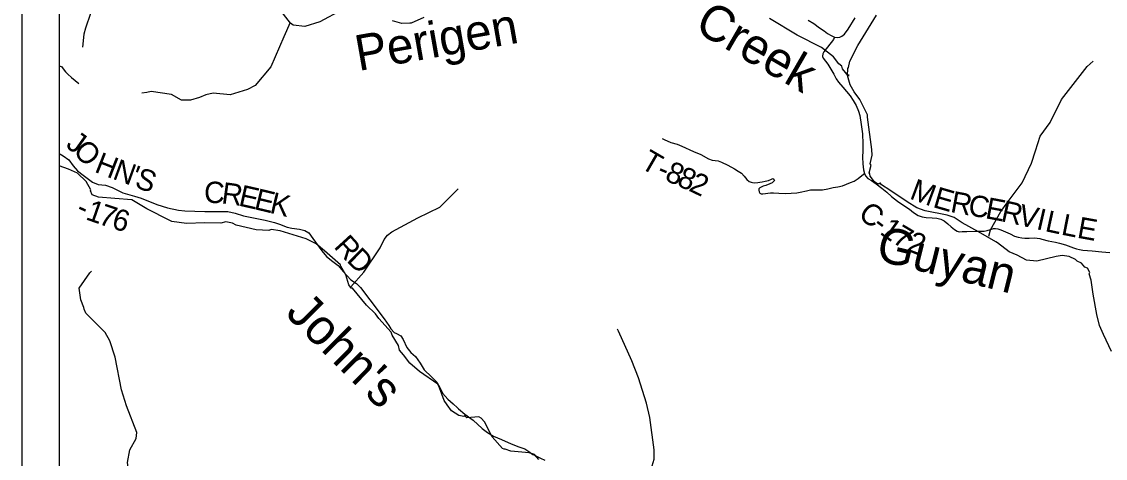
# Model space of a CAD drawing. Extents: x -1.8 to 75.7, y -2 to 25.
# Drawn here: x 43.7 to 46.582, y 17.434 to 18.595 of the extents above; entities that cross this region are included whole.
import ezdxf

# ---------------------------------------------------------------- set-up
doc = ezdxf.new("R2010")
doc.units = 0
for name, color, linetype in [('GM_X_County_Road', 7, 'Continuous'), ('GM_X_County_Road_Text', 7, 'Continuous'), ('GM_X_Minor_River', 7, 'Continuous'), ('GM_X_Minor_River_Text', 7, 'Continuous'), ('GM_X_State_Route', 7, 'Continuous'), ('GM_X_Township', 7, 'Continuous'), ('GM_X_Township_Road', 7, 'Continuous'), ('GM_X_Township_Road_Text', 7, 'Continuous'), ('SH_Data', 7, 'Continuous')]:
    doc.layers.add(name, color=color, linetype=linetype)

msp = doc.modelspace()

# ---------------------------------------------------------------- linework, layer by layer
at = {"layer": 'GM_X_County_Road'}
for points in [[(45.8619, 18.5535), (45.8589, 18.5478), (45.8339, 18.515), (45.8307, 18.5096), (45.8298, 18.5031)], [(45.8298, 18.5031), (45.8298, 18.5028), (45.8313, 18.498), (45.8376, 18.4898), (45.844, 18.4824), (45.8493, 18.4735), (45.8552, 18.4645), (45.8601, 18.455), (45.8664, 18.443), (45.8723, 18.434), (45.8843, 18.4208), (45.894, 18.4096), (45.9032, 18.3978), (45.9113, 18.3858), (45.9191, 18.3718), (45.9254, 18.3574), (45.9288, 18.3456), (45.9331, 18.3214), (45.9359, 18.2972), (45.9369, 18.2704), (45.9371, 18.2515), (45.9365, 18.235), (45.9369, 18.2175), (45.9386, 18.2013), (45.9416, 18.1915), (45.9443, 18.1848), (45.9506, 18.1785), (45.9603, 18.1728), (45.9727, 18.164), (45.9874, 18.1527), (46.0012, 18.1415), (46.0134, 18.1305), (46.0295, 18.1181), (46.0487, 18.1048), (46.061, 18.0963), (46.0719, 18.0877), (46.0845, 18.0802), (46.0952, 18.0761), (46.1059, 18.0746), (46.1216, 18.074), (46.1338, 18.0727), (46.1447, 18.0697), (46.1533, 18.0652), (46.1637, 18.0573), (46.1721, 18.05), (46.1809, 18.0427), (46.1882, 18.0382), (46.1933, 18.0365), (46.2012, 18.037), (46.2141, 18.0376), (46.2368, 18.038), (46.2601, 18.0382), (46.2676, 18.0395), (46.279, 18.0432), (46.285, 18.0449), (46.2901, 18.0453), (46.2965, 18.0445), (46.3042, 18.0421), (46.3289, 18.0307), (46.3406, 18.0252), (46.3505, 18.022), (46.3597, 18.02), (46.3683, 18.0192), (46.3798, 18.0192), (46.3931, 18.02), (46.401, 18.0196), (46.4077, 18.019), (46.4135, 18.0168), (46.4302, 18.0121), (46.4492, 18.0085), (46.4606, 18.0065), (46.4764, 18.0014), (46.4978, 17.9939), (46.5055, 17.9916), (46.5135, 17.9898), (46.5227, 17.9879), (46.5475, 17.9856), (46.5726, 17.9832), (46.5938, 17.9811)], [(43.8002, 18.2448), (43.8107, 18.2383), (43.8257, 18.2278), (43.8369, 18.2121), (43.849, 18.1989), (43.8637, 18.1873), (43.8745, 18.1788), (43.8884, 18.168), (43.9036, 18.1624), (43.9233, 18.1606), (43.9412, 18.1539), (43.9688, 18.1398), (44.0001, 18.1308), (44.0178, 18.1255), (44.0597, 18.1093), (44.0884, 18.0999), (44.1168, 18.0939), (44.1341, 18.0919), (44.1872, 18.0905), (44.2481, 18.0901), (44.2676, 18.086), (44.2902, 18.0786), (44.3475, 18.067), (44.3729, 18.0616), (44.3861, 18.0571), (44.4058, 18.0491), (44.4188, 18.0459), (44.4387, 18.0436), (44.4528, 18.0397), (44.4636, 18.0334), (44.4748, 18.0186), (44.4983, 17.9859), (44.5106, 17.9711), (44.5276, 17.9575), (44.5422, 17.9465), (44.5561, 17.9301), (44.5758, 17.9091), (44.5906, 17.8992), (44.6011, 17.8883), (44.6262, 17.8558), (44.6643, 17.8047), (44.6763, 17.7877), (44.6819, 17.7785), (44.6912, 17.7689), (44.6966, 17.7662)], [(44.6966, 17.7662), (44.7088, 17.7599), (44.7144, 17.7501), (44.7245, 17.7288), (44.7353, 17.7153), (44.7474, 17.7046), (44.7597, 17.6873), (44.7706, 17.6699), (44.7904, 17.6506), (44.804, 17.6365), (44.8123, 17.6226), (44.8197, 17.6072), (44.8334, 17.5919), (44.8477, 17.5796), (44.8588, 17.5685)], [(44.8588, 17.5685), (44.8616, 17.5657), (44.8788, 17.5521), (44.9008, 17.5357), (44.9252, 17.5138), (44.9393, 17.5026), (44.9552, 17.4934), (44.976, 17.4842), (45.0016, 17.4732), (45.022, 17.4652), (45.0379, 17.4593), (45.0493, 17.4526), (45.0596, 17.4448), (45.0608, 17.4442)], [(45.0608, 17.4442), (45.08, 17.4349), (45.0918, 17.4291)]]:
    msp.add_lwpolyline(points, dxfattribs=at)
at = {"layer": 'GM_X_Minor_River'}
for points in [[(44.5528, 18.6262), (44.4927, 18.5942), (44.4534, 18.5823), (44.4224, 18.586), (44.4148, 18.5913), (44.3845, 18.6312)], [(43.8833, 18.617), (43.8701, 18.5778), (43.8652, 18.5615), (43.8615, 18.5269)], [(44.414, 18.5924), (44.3974, 18.555), (44.3632, 18.4748), (44.3212, 18.4256), (44.3009, 18.4149), (44.2547, 18.4008), (44.2091, 18.4045), (44.1901, 18.4009), (44.1732, 18.3935), (44.1488, 18.3859), (44.125, 18.3867), (44.0983, 18.4016), (44.0444, 18.409), (44.0327, 18.4071), (44.0194, 18.4049)], [(44.7694, 18.6059), (44.7358, 18.5906), (44.7324, 18.5906), (44.7112, 18.5905), (44.6862, 18.5969)], [(45.8973, 18.45), (45.8994, 18.4544), (45.8991, 18.4502), (45.8828, 18.4695), (45.8813, 18.4764), (45.8737, 18.4828), (45.8589, 18.5014), (45.8275, 18.5264), (45.7629, 18.5593), (45.6891, 18.6032)], [(46.5987, 17.718), (46.5775, 17.7635), (46.5665, 17.7878), (46.5597, 17.8167), (46.5498, 17.8703), (46.5445, 17.9075), (46.5388, 17.925), (46.5407, 17.928), (46.535, 17.9394), (46.5278, 17.9428), (46.5184, 17.9534), (46.507, 17.9583), (46.5032, 17.9629), (46.4858, 17.9708), (46.4677, 17.9738), (46.4514, 17.9711), (46.4004, 17.9588), (46.3728, 17.9614), (46.3475, 17.9747), (46.3263, 17.9834), (46.2953, 18.0069), (46.2911, 18.0095), (46.245, 18.0364), (46.2011, 18.0602), (46.1803, 18.0742), (46.1618, 18.0807), (46.1028, 18.0923), (46.0805, 18.1002), (46.0555, 18.1157), (46.0093, 18.1472), (45.987, 18.1616), (45.9836, 18.1669), (45.9814, 18.1646), (45.984, 18.1635), (45.9817, 18.1638), (45.9832, 18.1657), (45.9772, 18.1634), (45.9685, 18.1691), (45.9564, 18.1839), (45.956, 18.1904), (45.9541, 18.193), (45.9594, 18.2132), (45.9571, 18.217), (45.9616, 18.2398), (45.9609, 18.2554), (45.9494, 18.3412), (45.9494, 18.3469), (45.9294, 18.3883), (45.9138, 18.4088), (45.9032, 18.427), (45.8968, 18.4521), (45.8971, 18.4703), (45.899, 18.4734), (45.9024, 18.4897), (45.9236, 18.5316), (45.9737, 18.6119)], [(46.2721, 18.0246), (46.2766, 18.0415), (46.3042, 18.09), (46.3212, 18.1134), (46.3609, 18.1664), (46.386, 18.2188), (46.3968, 18.2518), (46.4085, 18.2902), (46.4354, 18.3269), (46.4655, 18.3878), (46.5336, 18.4757), (46.5499, 18.49)], [(44.617, 17.8411), (44.5799, 17.887), (44.5762, 17.887), (44.5701, 17.8957), (44.5621, 17.9223), (44.5493, 17.9451), (44.5477, 17.9485), (44.5054, 17.986), (44.4834, 18.0046), (44.4566, 18.0179), (44.3878, 18.0393), (44.3636, 18.0427), (44.3571, 18.04), (44.3242, 18.0419), (44.2706, 18.0543), (44.2607, 18.0592), (44.2433, 18.0626), (44.2297, 18.0591), (44.1874, 18.0605), (44.1383, 18.0589), (44.0993, 18.0641), (44.0944, 18.0664), (44.0331, 18.0978), (43.9934, 18.1216), (43.9477, 18.1246), (43.9046, 18.1283), (43.8876, 18.1347), (43.883, 18.1449), (43.8845, 18.1476), (43.8716, 18.17), (43.8489, 18.1927), (43.8244, 18.2033), (43.8002, 18.2118)], [(44.5757, 17.8903), (44.6099, 17.9295), (44.6539, 17.9935), (44.6644, 18.0159), (44.673, 18.0278), (44.6843, 18.0366), (44.7539, 18.0734), (44.8126, 18.1022), (44.8612, 18.1503)], [(43.9314, 17.2896), (43.9461, 17.3223), (43.968, 17.3463), (43.9837, 17.3659), (43.9864, 17.392), (43.9817, 17.423), (43.9876, 17.4566), (44.0044, 17.4875), (44.0064, 17.5034), (43.9791, 17.5738), (43.9656, 17.6167), (43.949, 17.7031), (43.9344, 17.7465), (43.9226, 17.7685), (43.8712, 17.8202), (43.8666, 17.8306), (43.8653, 17.8356), (43.8576, 17.856), (43.8528, 17.8865), (43.8817, 17.9274), (43.8863, 17.9318)], [(45.0756, 17.4315), (45.0638, 17.4443), (45.0498, 17.4493), (45.0014, 17.4537), (44.9863, 17.459), (44.9833, 17.459), (44.9791, 17.4601), (44.9511, 17.4919), (44.9307, 17.531), (44.9224, 17.5413), (44.9159, 17.5443), (44.8838, 17.5419), (44.8789, 17.5469), (44.8759, 17.5457), (44.8626, 17.5483), (44.843, 17.5608), (44.8316, 17.5768), (44.824, 17.5878), (44.8089, 17.6284), (44.807, 17.6318), (44.7586, 17.6651), (44.7325, 17.6871), (44.7154, 17.7091), (44.7052, 17.7216), (44.7026, 17.7342), (44.6851, 17.7619), (44.6825, 17.7695), (44.6499, 17.8059), (44.6409, 17.8184), (44.617, 17.8411)], [(45.3634, 17.3541), (45.3715, 17.3971), (45.382, 17.4317), (45.382, 17.4571), (45.371, 17.5429), (45.3616, 17.5812), (45.3409, 17.6483), (45.323, 17.6933), (45.2876, 17.7726), (45.2847, 17.7773)]]:
    msp.add_lwpolyline(points, dxfattribs=at)
at = {"layer": 'GM_X_State_Route'}
msp.add_lwpolyline([(45.7914, 18.5993), (45.8068, 18.5898), (45.822, 18.5789), (45.834, 18.5706), (45.8433, 18.5639), (45.8526, 18.558), (45.8619, 18.5535), (45.8687, 18.5527), (45.876, 18.5537), (45.8813, 18.5562), (45.8883, 18.5615), (45.8978, 18.575), (45.9172, 18.6054)], dxfattribs=at)
at = {"layer": 'GM_X_Township'}
msp.add_lwpolyline([(43.8002, 18.978), (43.8002, 15.7121), (47.7632, 15.7121)], dxfattribs=at)
at = {"layer": 'GM_X_Township_Road'}
for points in [[(43.8002, 18.4774), (43.8011, 18.4775), (43.8071, 18.475), (43.8109, 18.4694), (43.8169, 18.4619), (43.8226, 18.4555), (43.8327, 18.4466), (43.8525, 18.4306)], [(45.4033, 18.2842), (45.4086, 18.2816), (45.4263, 18.274), (45.4433, 18.2692), (45.4557, 18.2641), (45.4871, 18.2496), (45.5066, 18.2415), (45.5267, 18.2301), (45.5362, 18.2269), (45.5525, 18.2254), (45.5615, 18.2214), (45.5785, 18.2137), (45.5958, 18.2035), (45.606, 18.1972), (45.6149, 18.1923), (45.6212, 18.184), (45.6289, 18.1756), (45.6352, 18.1703), (45.6401, 18.1683), (45.644, 18.1671), (45.6499, 18.1669), (45.6584, 18.1673), (45.6629, 18.1681), (45.6698, 18.1693), (45.6779, 18.1706), (45.6863, 18.1732), (45.6942, 18.1767), (45.6975, 18.1779), (45.7009, 18.1764), (45.7019, 18.1728), (45.6999, 18.1702), (45.6958, 18.1669), (45.6895, 18.1643), (45.679, 18.1596), (45.6722, 18.1574), (45.6631, 18.1535), (45.6609, 18.1506), (45.6605, 18.147), (45.6615, 18.1425), (45.6631, 18.1388), (45.6668, 18.1378), (45.6716, 18.1378), (45.6781, 18.1384), (45.6842, 18.139), (45.6916, 18.1401), (45.6993, 18.1401), (45.7141, 18.1392), (45.7328, 18.1386), (45.7465, 18.139), (45.7615, 18.1399), (45.7708, 18.1421), (45.7871, 18.1455), (45.7979, 18.1476), (45.8064, 18.1482), (45.82, 18.1478), (45.83, 18.1482), (45.8442, 18.1506), (45.8579, 18.1543), (45.8707, 18.1557), (45.8835, 18.1586), (45.8936, 18.1628), (45.9044, 18.1673), (45.9142, 18.171), (45.9195, 18.1744), (45.9251, 18.1781), (45.9347, 18.186), (45.9416, 18.1915)]]:
    msp.add_lwpolyline(points, dxfattribs=at)
at = {"layer": 'SH_Data'}
for p, q in [((43.7002, 22.6121), (43.7002, 15.6121)), ((43.8002, 22.5121), (43.8002, 15.7121)), ((43.8002, 22.5121), (43.8002, 15.7121))]:
    msp.add_line(p, q, dxfattribs=at)

# ---------------------------------------------------------------- texts
at = {"layer": 'GM_X_County_Road_Text'}
for s, rotation, p in [('J', 324.8161, (43.815, 18.2626)), ('O', 312.4504, (43.8344, 18.2493)), ('H', 338.6262, (43.8913, 18.1965)), ('N', 340.0241, (43.9393, 18.1778)), ('S', 339.5641, (43.9978, 18.1564)), ("'", 339.6384, (43.9861, 18.1607)), ('C', 358.3976, (44.1846, 18.1136)), ('R', 352.3609, (44.2297, 18.1124)), ('E', 347.2922, (44.2747, 18.1065)), ('M', 339.67, (46.0591, 18.1255)), ('E', 346.5843, (44.3159, 18.0972)), ('K', 346.5848, (44.3573, 18.0873)), ('E', 343.7296, (46.1211, 18.1027)), ('R', 349.4099, (46.1679, 18.0894)), ('C', 350.5171, (46.215, 18.0806)), ('E', 349.3137, (46.2607, 18.0729)), ('-', 335.3927, (43.8412, 18.082)), ('1', 340.8123, (43.8679, 18.0701)), ('7', 341.1906, (43.9013, 18.0585)), ('C', 321.9763, (45.9219, 18.0769)), ('R', 347.667, (46.302, 18.0651)), ('V', 347.0302, (46.3475, 18.0552)), ('6', 343.3419, (43.9367, 18.0465)), ('I', 347.0574, (46.3962, 18.044)), ('L', 347.6943, (46.4196, 18.0386)), ('L', 348.934, (46.4625, 18.0293)), ('E', 349.7491, (46.505, 18.021)), ('-', 322.995, (45.9596, 18.0475)), ('1', 324.6859, (45.9797, 18.0324)), ('7', 329.3821, (46.0125, 18.0094)), ('R', 312.3317, (44.5282, 17.9958)), ('2', 338.7231, (46.0517, 17.9871)), ('D', 315.5227, (44.562, 17.9589))]:
    msp.add_text(s, height=0.0568, rotation=rotation, dxfattribs=at).set_placement(p)
at = {"layer": 'GM_X_Minor_River_Text'}
for s, height, rotation, p in [('Creek', 0.09469, 330.0049, (45.4856, 18.5725)), ('Perigen', 0.0947, 10.0083, (44.5959, 18.4636)), ('Guyan', 0.09469, 346.0032, (45.9684, 17.9622)), ("John's", 0.09469, 315.0035, (44.3989, 17.8173))]:
    msp.add_text(s, height=height, rotation=rotation, dxfattribs=at).set_placement(p)
at = {"layer": 'GM_X_Township_Road_Text'}
for s, rotation, p in [('T', 329.8543, (45.3427, 18.2082)), ('8', 336.7416, (45.4078, 18.1743)), ('-', 337.0685, (45.3864, 18.1834)), ('8', 336.3405, (45.4399, 18.1605)), ('2', 334.5195, (45.4715, 18.1467))]:
    msp.add_text(s, height=0.0568, rotation=rotation, dxfattribs=at).set_placement(p)

doc.saveas('drawing.dxf')
